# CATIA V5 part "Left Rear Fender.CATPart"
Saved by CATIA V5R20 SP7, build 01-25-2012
Part number: Left Rear Fender
Bounding box of the stored display mesh (mm): x -496.521 to 425.059, y -80 to 100, z -6.699 to 429.99
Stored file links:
  E:\#03 University\#02 영남 이공대\#01 2021\#02 여름 방학\#01 Documents\K-Move Page02 ASD01\Left Rear Fender.CATPart

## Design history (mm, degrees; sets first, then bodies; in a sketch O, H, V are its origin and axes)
Set1 "Reference Data"
  Point1 "Center Point": (0, 0, 0)
  Plane1 "Plane.1(Y Dir=-80mm)": type Offset, RefPlane zx-plane, Offset 80, reversed
  Plane2 "Plane.2(Y Dir Plane.1=180mm)": type Offset, RefPlane Plane1, Offset 180
  Plane3 "Plane.3(Z Dir=65mm)": type Offset, RefPlane xy-plane, Offset 65
  Line1: type PtDir, LineFirstUpto Plane1, LineSecondUpto Plane2, RefPoint Point1, Direction zx-plane, Start 0, End 20
  Project1: ToProject Line1, Support Plane3
  Extrude1: Element1 Project1, Lim1 600, Lim2 0, Direction yz-plane
Body1 (main body)
  Body2
    Sketch1 on zx-plane, origin (0, 0, 0), H (-1, 0, 0), V (0, 0, 1)
      arc A1 centre (0, 0) radius 430 from (372.3909, 215) to (-425.0588, 65) ccw
      construction line L1 (0, 0) -> (372.3909, 215)
      point P1 (372.3909, 215)
      line L2 (372.3909, 215) -> (496.5212, 0)
      point P2 (496.5212, 0)
      point P4 (-425.0588, 65)
      reference intersected line E1 through (0, 65) direction (-1, 0) from Plane3
      radius A1 = 430
      angle L1 H = 30
      coincidence: P1 A1, P2 H, P1 L2, P4 E1
      tangency: L2 A1
    Pad1: profile Sketch1, direction (0, 1, 0), up to Plane2, opposite side up to Plane1, thin wall 50
    Fillet1: radius 50, on edge [face of Pad1 | face of Pad1]
    Fillet2: radius 30, on edge [face of Pad1 | end face of Pad1]
    Split1: SplitPlane Extrude1
    Shell1: ExtOffset 0, Face (face of Pad1; face of Split1; start face of Pad1), IntOffset 5
  Assemble1: tool Body2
